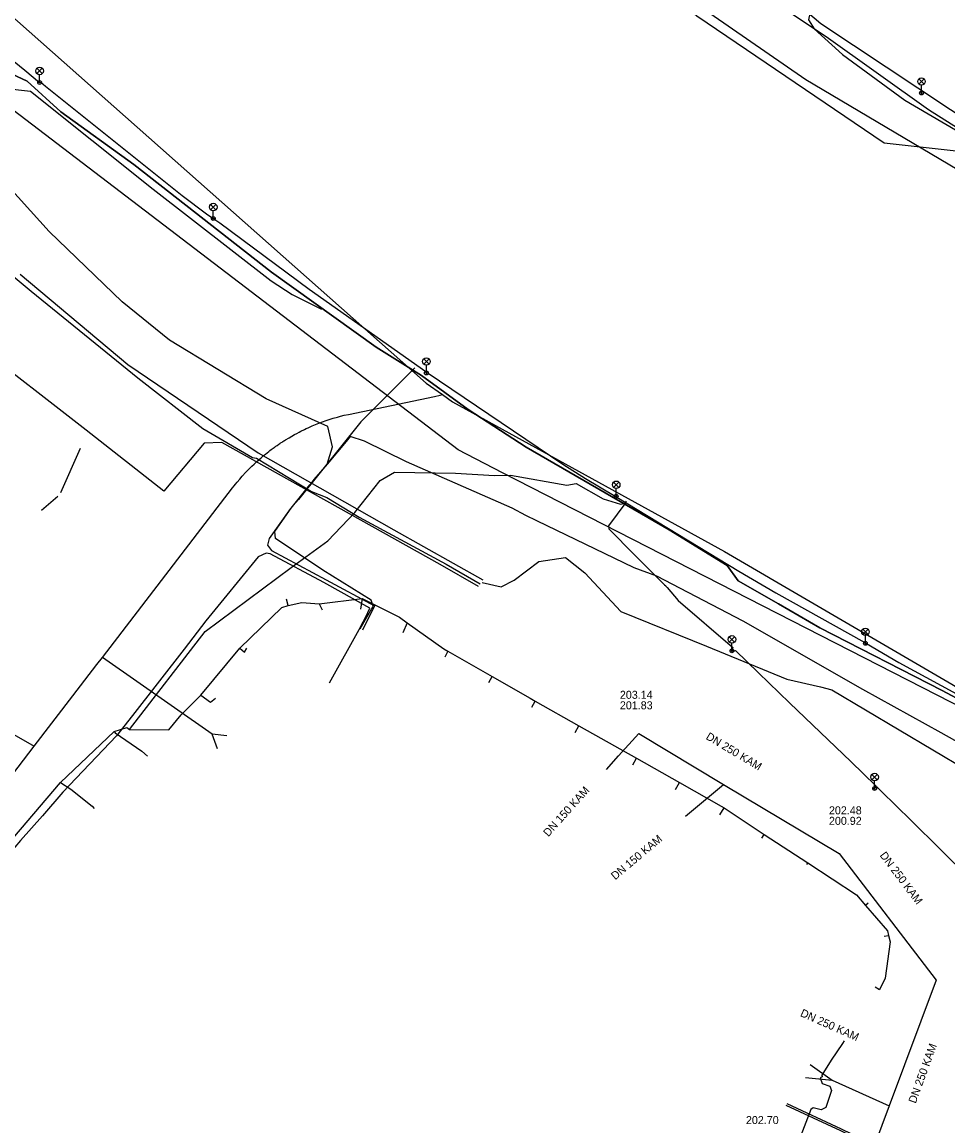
# Model space of a CAD drawing. Extents: x -598932 to -598196, y -1162210 to -1161504.
# Drawn here: x -598695.5 to -598603, y -1162086.4 to -1161976.1 of the extents above; entities that cross this region are included whole.
import ezdxf

# ---------------------------------------------------------------- set-up
doc = ezdxf.new("R2010")
doc.units = 0
for name, color, linetype in [('Vrstva 1', 7, 'Continuous'), ('Vrstva 12', 7, 'Continuous'), ('Vrstva 14', 7, 'Continuous'), ('Vrstva 19', 7, 'Continuous'), ('Vrstva 33', 7, 'Continuous'), ('Vrstva 42', 7, 'Continuous'), ('Vrstva 44', 7, 'Continuous'), ('Vrstva 53', 7, 'Continuous'), ('Vrstva 55', 7, 'Continuous'), ('Vrstva 58', 7, 'Continuous'), ('Vrstva 9', 7, 'Continuous')]:
    doc.layers.add(name, color=color, linetype=linetype)

msp = doc.modelspace()

# ---------------------------------------------------------------- linework, layer by layer
at = {"layer": 'Vrstva 1'}
for p, q in [((-598691.62, -1162023.12), (-598689.67, -1162018.68)), ((-598691.91, -1162023.51), (-598693.57, -1162024.92))]:
    msp.add_line(p, q, dxfattribs=at)
at = {"layer": 'Vrstva 12'}
msp.add_line((-598661.68, -1162036.55), (-598664.806, -1162042.185), dxfattribs=at)
msp.add_lwpolyline([(-598661.68, -1162036.55), (-598661.15, -1162035.55), (-598660.73, -1162034.67), (-598665.35, -1162032.12), (-598670.72, -1162029.25), (-598671.12, -1162029.18), (-598671.89, -1162029.56), (-598677.12, -1162035.93), (-598679.3, -1162038.79), (-598684.46, -1162045.42), (-598686.07, -1162047.45), (-598691.41, -1162053.08), (-598693.45, -1162055.45), (-598695.67, -1162057.92), (-598699.08, -1162061.9), (-598700.77, -1162065.9), (-598702.58, -1162070.91), (-598704.29, -1162074.31), (-598707.87, -1162079.18), (-598710.67, -1162083.24)], dxfattribs=at)
at = {"layer": 'Vrstva 14'}
msp.add_lwpolyline([(-598553.423, -1162069.27), (-598647.472, -1162021.146), (-598651.917, -1162018.863), (-598713.299, -1161971.957), (-598714.211, -1161971.254)], dxfattribs=at)
at = {"layer": 'Vrstva 19'}
for points in [[(-598609.34, -1161988.18), (-598628.06, -1161975.49), (-598652.04, -1161954.63), (-598675.39, -1161933.12)], [(-598526.7, -1162021.32), (-598533.53, -1162012.45), (-598534.5, -1162012.19), (-598579.8, -1162000.3), (-598601.83, -1161989.02), (-598609.34, -1161988.18)]]:
    msp.add_lwpolyline(points, dxfattribs=at)
at = {"layer": 'Vrstva 33'}
for p, q in [((-598694.009, -1161980.709), (-598693.479, -1161981.239)), ((-598694.009, -1161981.239), (-598693.479, -1161980.709)), ((-598693.744, -1161982.124), (-598693.744, -1161981.349)), ((-598605.875, -1161981.765), (-598605.345, -1161982.295)), ((-598605.875, -1161982.295), (-598605.345, -1161981.765)), ((-598605.61, -1161983.18), (-598605.61, -1161982.405)), ((-598676.651, -1161994.314), (-598676.121, -1161994.844)), ((-598676.651, -1161994.844), (-598676.121, -1161994.314)), ((-598676.386, -1161995.729), (-598676.386, -1161994.954)), ((-598655.355, -1162009.755), (-598654.825, -1162010.285)), ((-598655.355, -1162010.285), (-598654.825, -1162009.755)), ((-598655.09, -1162011.17), (-598655.09, -1162010.395)), ((-598636.382, -1162022.079), (-598635.852, -1162022.609)), ((-598636.382, -1162022.609), (-598635.852, -1162022.079)), ((-598636.117, -1162023.494), (-598636.117, -1162022.719)), ((-598611.475, -1162036.784), (-598610.945, -1162037.314)), ((-598611.475, -1162037.314), (-598610.945, -1162036.784)), ((-598624.819, -1162037.534), (-598624.289, -1162038.064)), ((-598624.819, -1162038.064), (-598624.289, -1162037.534)), ((-598624.554, -1162038.949), (-598624.554, -1162038.174)), ((-598611.21, -1162038.199), (-598611.21, -1162037.424)), ((-598610.56, -1162051.296), (-598610.03, -1162051.826)), ((-598610.56, -1162051.826), (-598610.03, -1162051.296)), ((-598610.295, -1162052.711), (-598610.295, -1162051.936))]:
    msp.add_line(p, q, dxfattribs=at)
for centre, radius in [((-598693.744, -1161980.974), 0.375), ((-598605.61, -1161982.03), 0.375), ((-598693.744, -1161982.124), 0.19), ((-598693.744, -1161982.124), 0.05), ((-598605.61, -1161983.18), 0.19), ((-598605.61, -1161983.18), 0.05), ((-598676.386, -1161994.579), 0.375), ((-598676.386, -1161995.729), 0.19), ((-598676.386, -1161995.729), 0.05), ((-598655.09, -1162010.02), 0.375), ((-598655.09, -1162011.17), 0.19), ((-598655.09, -1162011.17), 0.05), ((-598636.117, -1162022.344), 0.375), ((-598636.117, -1162023.494), 0.19), ((-598636.117, -1162023.494), 0.05), ((-598611.21, -1162037.049), 0.375), ((-598624.554, -1162037.799), 0.375), ((-598611.21, -1162038.199), 0.19), ((-598611.21, -1162038.199), 0.05), ((-598624.554, -1162038.949), 0.19), ((-598624.554, -1162038.949), 0.05), ((-598610.295, -1162051.561), 0.375), ((-598610.295, -1162052.711), 0.19), ((-598610.295, -1162052.711), 0.05)]:
    msp.add_circle(centre, radius, dxfattribs=at)
at = {"layer": 'Vrstva 42'}
for p, q in [((-598695.701, -1162001.277), (-598684.943, -1162010.329)), ((-598684.943, -1162010.329), (-598671.893, -1162019.136)), ((-598671.893, -1162019.136), (-598658.338, -1162026.863)), ((-598672.07, -1162019.69), (-598666.58, -1162023.02)), ((-598666.58, -1162023.02), (-598665.04, -1162023.62)), ((-598658.338, -1162026.863), (-598649.433, -1162031.857))]:
    msp.add_line(p, q, dxfattribs=at)
for points in [[(-598696.43, -1161910.03), (-598694.81, -1161909.35), (-598691.6, -1161908.88), (-598690.47, -1161909.23), (-598684.69, -1161915.57), (-598676.56, -1161921.46), (-598666.44, -1161931.11), (-598661.49, -1161936.08), (-598655.62, -1161944.08), (-598644.64, -1161954.28), (-598635.19, -1161962.23), (-598623.88, -1161971.66), (-598615.13, -1161977.53), (-598604.9, -1161984.84), (-598594.32, -1161991.54), (-598583.95, -1161997.32), (-598575.77, -1162001.27), (-598572.76, -1162002.34), (-598572.68, -1162003.32), (-598572.43, -1162007.67)], [(-598616.75, -1161975.23), (-598616.89, -1161975.85), (-598616.35, -1161976.76), (-598613.51, -1161979.33), (-598607.26, -1161983.88), (-598596.76, -1161990.06), (-598589.11, -1161994.85), (-598579.94, -1161999.61), (-598579.286, -1161999.751)], [(-598584.94, -1162048.187), (-598587.373, -1162051.113), (-598590.418, -1162054.759), (-598591.461, -1162054.798), (-598592.644, -1162051.677), (-598594.475, -1162048.726), (-598595.514, -1162047.861), (-598598.175, -1162045.777), (-598603.555, -1162042.914), (-598615.772, -1162036.634), (-598619.898, -1162034.24), (-598623.918, -1162031.949), (-598625.034, -1162030.4), (-598630.842, -1162026.844), (-598645.114, -1162018.576), (-598650.929, -1162014.808), (-598655.57, -1162011.409), (-598660.099, -1162008.595), (-598670.573, -1162001.081), (-598684.323, -1161990.333), (-598691.62, -1161985.078), (-598695, -1161981.986), (-598698.099, -1161980.56)], [(-598725.71, -1162005.966), (-598724.36, -1162006.13), (-598723.33, -1162006.02), (-598721.93, -1162004.53), (-598721.33, -1162003.77), (-598716.38, -1161997.42), (-598715.62, -1161996.44), (-598710.86, -1161991.48), (-598708.32, -1161989.86), (-598705.27, -1161991.6), (-598701.2, -1161994.85), (-598700.27, -1161996.12), (-598697.18, -1162000.81), (-598694.58, -1162003), (-598683.93, -1162011.64), (-598677.43, -1162016.73), (-598672.47, -1162019.63), (-598672.07, -1162019.69)], [(-598649.876, -1162032.498), (-598653.71, -1162030.33), (-598675.54, -1162018.13), (-598677.3, -1162018.19), (-598681.33, -1162022.99), (-598689.1, -1162016.9), (-598700.37, -1162008.16), (-598711.63, -1161999.39), (-598712.26, -1161999.9), (-598717.71, -1162006.96), (-598719.43, -1162009.12), (-598720.65, -1162009.02), (-598722.88, -1162007.29), (-598725.78, -1162005.18), (-598726.086, -1162005.596)], [(-598665.04, -1162023.62), (-598661.82, -1162025.58), (-598653.1, -1162030.28), (-598649.701, -1162032.255)], [(-598649.502, -1162032.103), (-598647.624, -1162032.536), (-598646.31, -1162031.88), (-598643.86, -1162030.02), (-598641.2, -1162029.6), (-598639.24, -1162031.15), (-598635.67, -1162035), (-598627.11, -1162038.48), (-598619.07, -1162041.79), (-598615.71, -1162042.56), (-598614.58, -1162042.86), (-598601.101, -1162050.854), (-598591.558, -1162056.282), (-598591.22, -1162058.33), (-598591.5, -1162059.05), (-598592.24, -1162060.76), (-598591.784, -1162061.026)], [(-598649.502, -1162032.103), (-598647.624, -1162032.536), (-598646.31, -1162031.88), (-598643.86, -1162030.02), (-598641.2, -1162029.6), (-598639.24, -1162031.15), (-598635.67, -1162035), (-598627.11, -1162038.48), (-598619.07, -1162041.79), (-598615.71, -1162042.56), (-598614.58, -1162042.86), (-598601.101, -1162050.854), (-598591.558, -1162056.282), (-598591.22, -1162058.33), (-598591.5, -1162059.05), (-598592.24, -1162060.76), (-598591.784, -1162061.026)], [(-598649.502, -1162032.103), (-598647.624, -1162032.536), (-598646.31, -1162031.88)]]:
    msp.add_lwpolyline(points, dxfattribs=at)
at = {"layer": 'Vrstva 44'}
for points in [[(-598619.153, -1162084.363), (-598613.716, -1162086.904), (-598606.953, -1162090.175), (-598605.727, -1162092.3), (-598607.4, -1162097.997), (-598607.089, -1162099.763), (-598607.885, -1162104.838), (-598605.856, -1162106.119), (-598574.908, -1162116.065), (-598574.461, -1162116.139), (-598575.191, -1162117.929)], [(-598619.069, -1162084.181), (-598613.63, -1162086.724), (-598606.811, -1162090.021), (-598605.511, -1162092.274), (-598607.194, -1162098.009), (-598606.887, -1162099.761), (-598607.667, -1162104.74), (-598605.77, -1162105.937), (-598574.86, -1162115.871), (-598574.389, -1162115.947), (-598573.945, -1162114.598)]]:
    msp.add_lwpolyline(points, dxfattribs=at)
at = {"layer": 'Vrstva 53'}
for points in [[(-598665, -1162020.27), (-598664.48, -1162018.55), (-598664.95, -1162016.51), (-598671.12, -1162013.75), (-598680.78, -1162007.89), (-598685.51, -1162004.04), (-598692.78, -1161997.01), (-598697.79, -1161991.52), (-598700.67, -1161987.75), (-598701.13, -1161987.23)], [(-598591.6, -1162056.38), (-598591.95, -1162055.74), (-598592.23, -1162054.45), (-598594.42, -1162052.8), (-598600.38, -1162048.96), (-598603.64, -1162047.13), (-598611.48, -1162042.8), (-598623.43, -1162035.99), (-598632.06, -1162031.49), (-598634.31, -1162030.66), (-598644.06, -1162025.96), (-598645.14, -1162025.4), (-598646.52, -1162024.69), (-598657.07, -1162020.06), (-598661.29, -1162018), (-598662.7, -1162017.52), (-598663.12, -1162018.01), (-598665, -1162020.27)], [(-598665, -1162020.27), (-598666.34, -1162021.83), (-598666.75, -1162022.342)], [(-598661.71, -1162036.745), (-598660.421, -1162034.496), (-598660.601, -1162033.886), (-598665.444, -1162030.873), (-598670.168, -1162027.703), (-598670.233, -1162027.021), (-598668.611, -1162024.685), (-598666.75, -1162022.342)]]:
    msp.add_lwpolyline(points, dxfattribs=at)
at = {"layer": 'Vrstva 55'}
for p, q in [((-598668.9, -1162034.4), (-598669.07, -1162033.78)), ((-598665.82, -1162034.24), (-598661.5, -1162033.72)), ((-598661.5, -1162033.72), (-598661.68, -1162034.77)), ((-598665.82, -1162034.24), (-598665.5, -1162034.85)), ((-598657.01, -1162036.13), (-598657.46, -1162037.14)), ((-598677.63, -1162043.39), (-598673.73, -1162038.68)), ((-598652.96, -1162038.98), (-598653.25, -1162039.59)), ((-598652.96, -1162038.98), (-598648.53, -1162041.51)), ((-598648.86, -1162042.11), (-598648.53, -1162041.51)), ((-598644.55, -1162044.59), (-598644.21, -1162043.98)), ((-598644.21, -1162043.98), (-598639.84, -1162046.44)), ((-598691.66, -1162052.1), (-598686.29, -1162047.02)), ((-598640.21, -1162047.1), (-598639.84, -1162046.44)), ((-598639.84, -1162046.44), (-598634.09, -1162049.67)), ((-598634.46, -1162050.35), (-598634.09, -1162049.67)), ((-598634.09, -1162049.67), (-598629.79, -1162052.1)), ((-598630.2, -1162052.8), (-598629.79, -1162052.1)), ((-598625.77, -1162055.33), (-598625.34, -1162054.65)), ((-598625.34, -1162054.65), (-598621.32, -1162057.29)), ((-598621.56, -1162057.66), (-598621.32, -1162057.29)), ((-598621.32, -1162057.29), (-598616.97, -1162060.15)), ((-598617.07, -1162060.3), (-598616.97, -1162060.15)), ((-598610.94, -1162064.17), (-598611.19, -1162064.39)), ((-598609.34, -1162067.46), (-598608.9, -1162067.39))]:
    msp.add_line(p, q, dxfattribs=at)
for points in [[(-598538.426, -1162013.595), (-598569.03, -1162006.79), (-598583.43, -1162000.81), (-598602.04, -1161990.84), (-598617.15, -1161981.87), (-598630.44, -1161972.68), (-598653.03, -1161953.63), (-598683.76, -1161922.51), (-598678.33, -1161917.53), (-598684.31, -1161911.55), (-598687.3, -1161909.33), (-598691.29, -1161908.33), (-598694.72, -1161908.89), (-598697.83, -1161910.55), (-598701.59, -1161914.87), (-598725.38, -1161945.83), (-598731.11, -1161953.74), (-598726.48, -1161957.43), (-598725.72, -1161956.78), (-598724.89, -1161957.11), (-598720.519, -1161951.972)], [(-598635.847, -1162206.96), (-598629.97, -1162189.7), (-598621.09, -1162162.42), (-598598.1, -1162097.33), (-598589.15, -1162070.89), (-598592.61, -1162069.46), (-598587.52, -1162054.61), (-598584.27, -1162048.71), (-598581.62, -1162049.12), (-598567.59, -1162009.46), (-598573.28, -1162007.22), (-598571.851, -1162001.315), (-598576.64, -1161997.21), (-598590.4, -1161991.37), (-598599.45, -1161987.03), (-598615.67, -1161976.28), (-598632.44, -1161961.96), (-598678.26, -1161917.47), (-598684.987, -1161911.745), (-598688.029, -1161910.224), (-598691.806, -1161909.122), (-598694.533, -1161909.122), (-598697.86, -1161910.3), (-598707.4, -1161922.62)], [(-598702.856, -1161974.747), (-598695.218, -1161980.89), (-598693.744, -1161982.124), (-598693.621, -1161982.109), (-598693.163, -1161982.481), (-598679.505, -1161993.43), (-598677.053, -1161995.251), (-598676.534, -1161995.627), (-598676.386, -1161995.729), (-598676.238, -1161995.833), (-598675.742, -1161996.163), (-598666.814, -1162002.795), (-598655.145, -1162011.031), (-598655.089, -1162011.17), (-598655.016, -1162011.113), (-598641.444, -1162020.294), (-598639.177, -1162021.707), (-598636.237, -1162023.485), (-598636.117, -1162023.494), (-598636.058, -1162023.593), (-598623.862, -1162030.968), (-598620.165, -1162033.14), (-598611.282, -1162038.098), (-598611.21, -1162038.199), (-598611.1, -1162038.2), (-598607.868, -1162040.118), (-598599.4, -1162044.712)], [(-598668.62, -1162030.6), (-598664.94, -1162027.95), (-598662.23, -1162025.11), (-598659.71, -1162021.91), (-598658.28, -1162021.07), (-598652.17, -1162021.19), (-598648.29, -1162021.43), (-598646.68, -1162021.37), (-598641.05, -1162022.38), (-598640.13, -1162022.22), (-598637.42, -1162023.76), (-598635.7, -1162024.29), (-598635.22, -1162024.17), (-598635.08, -1162023.99)], [(-598635.163, -1162024.131), (-598636.881, -1162026.435), (-598636.865, -1162026.765), (-598634.248, -1162029.378), (-598631.276, -1162032.338), (-598631.156, -1162032.458), (-598631.11, -1162032.512), (-598631.015, -1162032.623), (-598629.932, -1162033.901), (-598624.482, -1162038.594), (-598624.475, -1162038.601), (-598624.55, -1162038.95), (-598624.21, -1162038.915), (-598621.904, -1162041.14), (-598618.786, -1162044.137), (-598615.686, -1162047.118), (-598612.668, -1162050.024), (-598610.154, -1162052.446), (-598610.29, -1162052.7), (-598610.09, -1162052.51), (-598609.634, -1162052.959), (-598606.64, -1162055.919), (-598603.742, -1162058.78), (-598600.7, -1162061.781)], [(-598684.75, -1162046.8), (-598677.21, -1162037.01), (-598668.62, -1162030.6)], [(-598661.5, -1162033.72), (-598657.78, -1162035.59), (-598657.01, -1162036.13)], [(-598673.73, -1162038.68), (-598669.54, -1162034.62), (-598668.9, -1162034.4)], [(-598668.9, -1162034.4), (-598667.55, -1162034.11), (-598665.82, -1162034.24)], [(-598657.01, -1162036.13), (-598653.35, -1162038.76), (-598652.96, -1162038.98)], [(-598673.73, -1162038.68), (-598673.26, -1162039.08), (-598673.04, -1162038.69)], [(-598648.53, -1162041.51), (-598644.72, -1162043.69), (-598644.21, -1162043.98)], [(-598684.75, -1162046.8), (-598680.84, -1162046.83), (-598679.6, -1162045.35), (-598677.63, -1162043.39)], [(-598677.63, -1162043.39), (-598676.66, -1162044.09), (-598676.16, -1162043.68)], [(-598686.29, -1162047.02), (-598685.04, -1162046.61), (-598684.75, -1162046.8)], [(-598686.29, -1162047.02), (-598686.18, -1162047.15), (-598683.54, -1162048.97), (-598682.96, -1162049.48)], [(-598706.66, -1162072.58), (-598706.1, -1162071.61), (-598699.69, -1162061.51), (-598691.66, -1162052.1)], [(-598691.66, -1162052.1), (-598690.64, -1162052.79), (-598688.48, -1162054.48), (-598688.29, -1162054.7)], [(-598629.79, -1162052.1), (-598625.63, -1162054.46), (-598625.34, -1162054.65)], [(-598616.97, -1162060.15), (-598612.09, -1162063.35), (-598611.19, -1162064.39)], [(-598611.19, -1162064.39), (-598609, -1162066.94), (-598608.9, -1162067.39)], [(-598608.9, -1162067.39), (-598608.74, -1162068.03), (-598609.24, -1162071.66), (-598609.8, -1162072.84), (-598610.25, -1162072.58)], [(-598613.35, -1162077.93), (-598613.5, -1162078.21), (-598614.65, -1162079.88), (-598615.58, -1162081.35), (-598615.52, -1162081.52), (-598615.75, -1162081.62), (-598615.54, -1162082.2), (-598614.77, -1162082.45), (-598614.61, -1162082.89), (-598615.18, -1162084.59), (-598615.63, -1162084.84), (-598616.42, -1162084.62), (-598616.66, -1162084.8), (-598618.18, -1162088.68), (-598618.32, -1162088.91), (-598618.53, -1162088.83), (-598618.83, -1162088.91), (-598620.6, -1162093.84)]]:
    msp.add_lwpolyline(points, dxfattribs=at)
at = {"layer": 'Vrstva 58'}
for points in [[(-598703.395, -1161978.841), (-598699.591, -1161979.981), (-598698.099, -1161980.56), (-598695, -1161981.986), (-598691.62, -1161985.078), (-598684.323, -1161990.333), (-598670.573, -1162001.081), (-598660.099, -1162008.595), (-598655.57, -1162011.409), (-598650.929, -1162014.808), (-598645.114, -1162018.576), (-598630.842, -1162026.844), (-598625.034, -1162030.4), (-598623.918, -1162031.949), (-598619.898, -1162034.24), (-598615.772, -1162036.634), (-598603.555, -1162042.914), (-598598.175, -1162045.777), (-598594.475, -1162048.726), (-598592.644, -1162051.677), (-598591.461, -1162054.798), (-598590.418, -1162054.759), (-598587.373, -1162051.113), (-598584.94, -1162048.187)], [(-598705.64, -1161986.79), (-598702.49, -1161983.64), (-598697.32, -1161982.7), (-598694.66, -1161982.99), (-598682.41, -1161992.78), (-598670.6, -1162001.95), (-598668.52, -1162003.31), (-598665.58, -1162004.79)], [(-598656.23, -1162010.65), (-598661.65, -1162016.06), (-598667.86, -1162023.83), (-598668.67, -1162024.7), (-598670.79, -1162027.72), (-598670.96, -1162028.37), (-598670.57, -1162028.92), (-598665.11, -1162031.85), (-598660.27, -1162034.45), (-598661.47, -1162036.87)]]:
    msp.add_lwpolyline(points, dxfattribs=at)
at = {"layer": 'Vrstva 9'}
for p, q in [((-598676.496, -1162047.26), (-598687.477, -1162039.598)), ((-598699.155, -1162045.681), (-598694.293, -1162048.474)), ((-598675.031, -1162047.458), (-598676.496, -1162047.26)), ((-598675.983, -1162048.737), (-598676.496, -1162047.26)), ((-598635.89, -1162049.45), (-598633.85, -1162047.22)), ((-598637.103, -1162050.81), (-598635.89, -1162049.45)), ((-598629.19, -1162055.47), (-598625.383, -1162052.292)), ((-598613.82, -1162059.22), (-598604.15, -1162071.88)), ((-598604.15, -1162071.88), (-598608.83, -1162084.43)), ((-598616.744, -1162080.284), (-598614.53, -1162081.85)), ((-598617.21, -1162081.605), (-598614.53, -1162081.85)), ((-598614.53, -1162081.85), (-598608.83, -1162084.43))]:
    msp.add_line(p, q, dxfattribs=at)
for points in [[(-598726.057, -1161949.335), (-598655.105, -1162012.176), (-598653.484, -1162013.336)], [(-598667.639, -1162016.996), (-598667.284, -1162016.821), (-598667.095, -1162016.73), (-598666.912, -1162016.646), (-598666.511, -1162016.466), (-598665.837, -1162016.192), (-598665.122, -1162015.93), (-598664.398, -1162015.697), (-598663.972, -1162015.574), (-598663.671, -1162015.492), (-598663.317, -1162015.402), (-598662.891, -1162015.303), (-598654.292, -1162013.529), (-598653.71, -1162013.388), (-598653.484, -1162013.336)], [(-598653.484, -1162013.336), (-598652.475, -1162014.059), (-598625.289, -1162029.029), (-598589.053, -1162050.166), (-598581.324, -1162054.674)], [(-598698.051, -1162053.368), (-598694.293, -1162048.474), (-598690.438, -1162043.454), (-598688.02, -1162040.305), (-598687.477, -1162039.598), (-598674.468, -1162022.658), (-598674.31, -1162022.458), (-598674.169, -1162022.281), (-598674.004, -1162022.075), (-598673.746, -1162021.774), (-598673.495, -1162021.487), (-598673.137, -1162021.097), (-598672.74, -1162020.688), (-598672.537, -1162020.49), (-598672.308, -1162020.271), (-598672.069, -1162020.05), (-598671.802, -1162019.811), (-598671.604, -1162019.64), (-598671.36, -1162019.434), (-598671.187, -1162019.292), (-598670.837, -1162019.016), (-598670.77, -1162018.964), (-598670.723, -1162018.928), (-598670.595, -1162018.831), (-598670.308, -1162018.62), (-598670.26, -1162018.585), (-598670.239, -1162018.571), (-598670.186, -1162018.533), (-598670.127, -1162018.491), (-598670.013, -1162018.411), (-598669.825, -1162018.282), (-598669.747, -1162018.23), (-598669.686, -1162018.189), (-598669.655, -1162018.168), (-598669.518, -1162018.079), (-598669.445, -1162018.031), (-598669.337, -1162017.963), (-598669.257, -1162017.912), (-598669.163, -1162017.853), (-598668.807, -1162017.636), (-598668.543, -1162017.482), (-598668.267, -1162017.328), (-598668.049, -1162017.209), (-598667.819, -1162017.088), (-598667.639, -1162016.996)], [(-598633.85, -1162047.22), (-598625.383, -1162052.292), (-598613.82, -1162059.22)], [(-598608.83, -1162084.43), (-598613.98, -1162098.178), (-598616.11, -1162103.862), (-598626.44, -1162131.43)]]:
    msp.add_lwpolyline(points, dxfattribs=at)

# ---------------------------------------------------------------- texts
at = {"layer": 'Vrstva 12'}
for s, p in [('203.14', (-598635.751, -1162043.74)), ('201.83', (-598635.751, -1162044.79)), ('202.48', (-598614.855, -1162055.289)), ('200.92', (-598614.855, -1162056.339)), ('202.70', (-598623.152, -1162086.252))]:
    msp.add_text(s, height=0.8, dxfattribs=at).set_placement(p)
for s, rotation, p in [('DN 250 KAM', 329, (-598627.225, -1162047.727)), ('DN 150 KAM', 48, (-598642.904, -1162057.583)), ('DN 150 KAM', 40, (-598636.222, -1162061.893)), ('DN 250 KAM', 307, (-598609.824, -1162059.398)), ('DN 250 KAM', 336, (-598617.788, -1162075.435)), ('DN 250 KAM', 70, (-598606.191, -1162084.246))]:
    msp.add_text(s, height=0.8, rotation=rotation, dxfattribs=at).set_placement(p)

doc.saveas('drawing.dxf')
